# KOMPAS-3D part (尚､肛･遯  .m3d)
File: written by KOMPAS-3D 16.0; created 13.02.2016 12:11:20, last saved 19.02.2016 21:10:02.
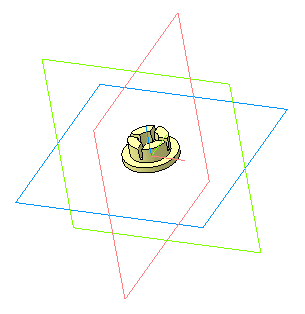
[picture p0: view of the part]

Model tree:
1. Эскиз:1
2. Операция выдавливания:1
     Расстояние 1 = 1.5
3. Эскиз:2
4. Операция выдавливания:2
     Расстояние 1 = 4
5. Эскиз:3
6. Вырезать элемент выдавливания:1
     Расстояние 1 = 22
7. Эскиз:4
8. Вырезать элемент выдавливания:2
     Расстояние 1 = 3
9. Фаска:2
     Угол = 5; Длина 1 = 8.0001; Длина 2 = 0.699918
10. Фаска:3
     Угол = 5; Длина 1 = 8.0001; Длина 2 = 0.699918
11. Фаска:4
     Угол = 5; Длина 1 = 8.0001; Длина 2 = 0.699918
12. Фаска:5
     Угол = 5; Длина 1 = 8.0001; Длина 2 = 0.699918
13. Фаска:6
     Угол = 5; Длина 1 = 8.0001; Длина 2 = 0.699918
14. Фаска:7
     Угол = 5; Длина 1 = 8.0001; Длина 2 = 0.699918
15. Фаска:8
     Угол = 5; Длина 1 = 8.0001; Длина 2 = 0.699918
16. Фаска:9
     Угол = 5; Длина 1 = 8.0001; Длина 2 = 0.699918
